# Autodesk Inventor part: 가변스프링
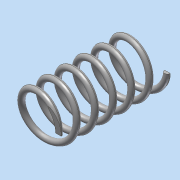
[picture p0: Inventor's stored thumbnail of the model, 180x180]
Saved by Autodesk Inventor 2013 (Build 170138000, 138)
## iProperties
Created: 2018-06
Part Number: 가변스프링
Material: 강철, 연강
Document SubType Name: Modeling
Designer: dgall
Density: 7.86 g/cm^3
Mass: -0.0883188 g
Surface Area: 18.9697 cm^2
Volume: -0.0112365 cm^3
Author: dgall
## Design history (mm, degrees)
sketch "스케치1"
  geometry: L1 (0, 0)-(0, 38); L2 (0, 38)-(8, 38); L3 (0, 0)-(8, 0); C1 r 1 at (8, 0)
  constraints: 6 end point, 2 parallel, 1 centre point, 1 coincident, 1 perpendicular, 1 vertical
  dimensions: "d0" = 38 distance of L1.start L1.end (derived); "d1" = 16 diameter of L2.end L1; "d2" = 1 radius of C1
feature "코일1" pitch "d3" = 10; turns "d5" = 6; dims "d4" = 37.99994 (computed from d0), "d6" = 0, angle "d7" = 90 deg, angle "d8" = 90 deg, "d9" = 0, "d10" = 0
feature "분할1"
node "작업 평면1"
feature "분할2"
node "솔리드1"
other parameters: "d11" = 0
